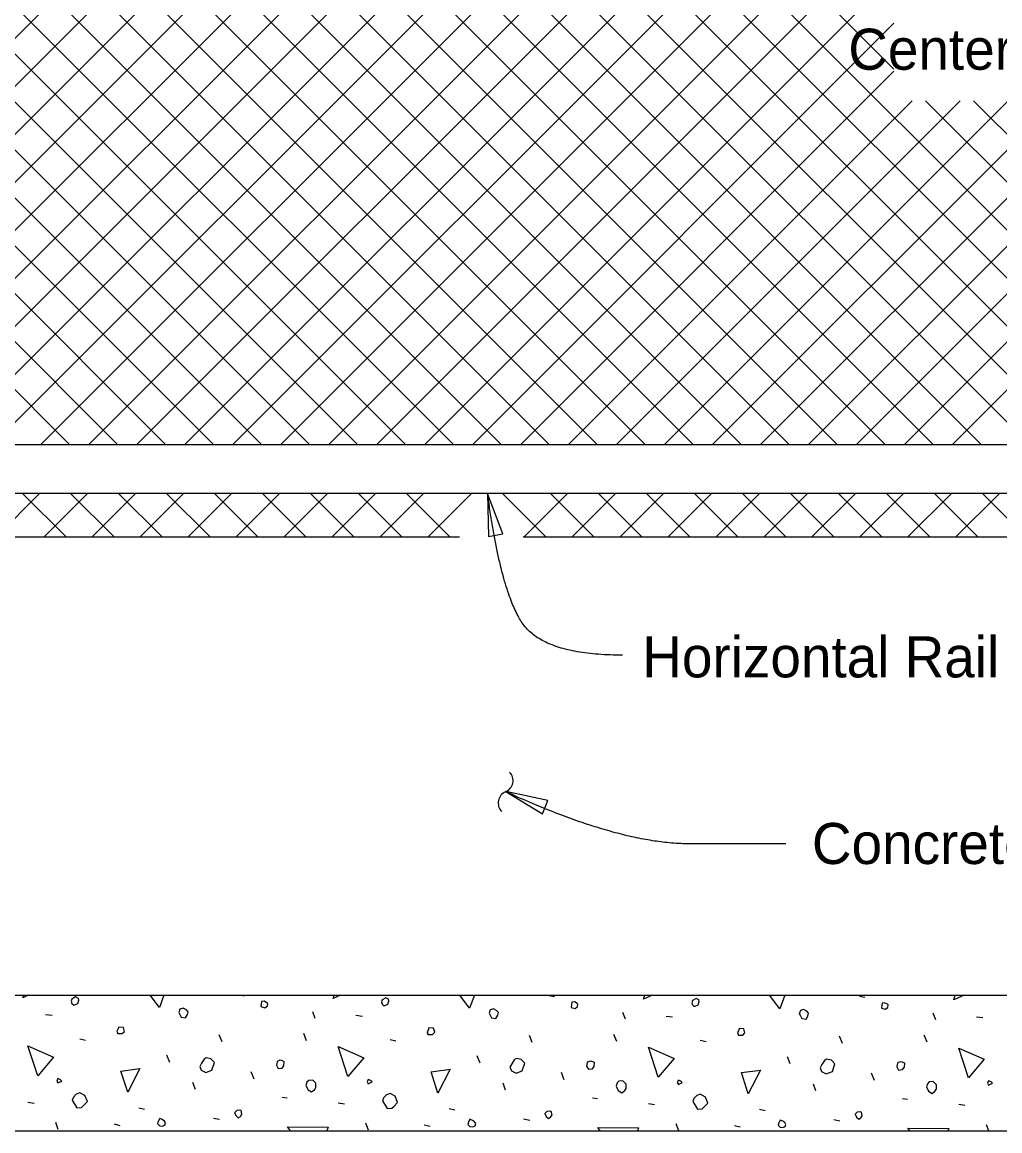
# Model space of a CAD drawing. Extents: x 0.4 to 38.5, y 1.2 to 25.4.
# Drawn here: x 3.07 to 7.87, y 14.04 to 19.49 of the extents above; entities that cross this region are included whole.
import ezdxf

# ---------------------------------------------------------------- set-up
doc = ezdxf.new("R2010")
doc.units = 0
for name, color, linetype in [('Dimension', 7, 'Continuous'), ('Miscellaneous', 7, 'Continuous'), ('SteelMisc', 7, 'Continuous'), ('SupstrConc', 7, 'Continuous'), ('TextStructures', 7, 'Continuous')]:
    doc.layers.add(name, color=color, linetype=linetype)

msp = doc.modelspace()

# ---------------------------------------------------------------- linework, layer by layer
at = {"layer": 'Dimension'}
for points in [[(5.3566, 17.1708), (5.3616, 16.9597), (5.4309, 16.9731)], [(5.4456, 15.7069), (5.6265, 15.5979), (5.6523, 15.6635)]]:
    msp.add_lwpolyline(points, close=True, dxfattribs=at)
for centre, start, end in [((5.4222, 15.7609), 292.7091, 44.4364), ((5.4682, 15.651), 112.7091, 224.4364)]:
    msp.add_arc(centre, 0.0596, start, end, dxfattribs=at)
for points in [[(6.0197, 16.3768), (5.6218, 16.3768), (5.4178, 16.7138), (5.3566, 17.1707)], [(6.8209, 15.4497), (6.7025, 15.4497), (6.0031, 15.4497), (5.4454, 15.7067)]]:
    msp.add_open_spline(points, degree=2, dxfattribs=at)
at = {"layer": 'Miscellaneous'}
for p, q in [((6.6877, 22.5875), (2.2208, 18.1206)), ((6.2163, 22.5875), (2.2208, 18.592)), ((6.452, 22.5875), (2.2208, 18.3563)), ((7.1591, 22.5875), (2.2208, 17.6492)), ((6.9234, 22.5875), (2.2208, 17.8849)), ((7.3948, 22.5875), (2.2704, 17.4631)), ((7.5471, 17.4104), (2.3872, 22.5703)), ((7.6305, 22.5875), (2.4688, 17.4258)), ((7.7828, 17.4104), (2.6043, 22.5889)), ((7.8662, 22.5875), (2.6891, 17.4104)), ((8.0185, 17.4104), (2.8414, 22.5875)), ((8.1019, 22.5875), (2.9248, 17.4104)), ((8.2542, 17.4104), (3.0771, 22.5875)), ((8.3376, 22.5875), (3.1605, 17.4104)), ((8.4899, 17.4104), (3.3128, 22.5875)), ((8.5733, 22.5875), (3.3962, 17.4104)), ((8.7256, 17.4104), (3.5485, 22.5875)), ((8.809, 22.5875), (3.6319, 17.4104)), ((8.9613, 17.4104), (3.7842, 22.5875)), ((9.0447, 22.5875), (3.8676, 17.4104)), ((7.352, 19.2554), (4.0199, 22.5875)), ((9.2804, 22.5875), (4.1033, 17.4104)), ((7.3114, 17.4104), (2.2208, 22.501)), ((7.0757, 17.4104), (2.2208, 22.2653)), ((6.84, 17.4104), (2.2208, 22.0296)), ((6.6043, 17.4104), (2.2208, 21.7939)), ((6.3686, 17.4104), (2.2208, 21.5582)), ((6.1329, 17.4104), (2.2208, 21.3225)), ((5.8972, 17.4104), (2.2208, 21.0868)), ((5.6615, 17.4104), (2.2208, 20.8511)), ((5.4258, 17.4104), (2.2208, 20.6154)), ((7.352, 20.4234), (4.339, 17.4104)), ((5.1901, 17.4104), (2.2208, 20.3797)), ((7.352, 20.1877), (4.5747, 17.4104)), ((4.9544, 17.4104), (2.2208, 20.1439)), ((7.352, 19.952), (4.8104, 17.4104)), ((4.7187, 17.4104), (2.2208, 19.9082)), ((7.352, 19.7163), (5.0461, 17.4104)), ((4.483, 17.4104), (2.2208, 19.6725)), ((7.352, 19.4806), (5.2818, 17.4104)), ((4.2473, 17.4104), (2.2208, 19.4368)), ((7.352, 19.2449), (5.5175, 17.4104)), ((4.0116, 17.4104), (2.2208, 19.2011)), ((7.4426, 19.0998), (5.7532, 17.4104)), ((7.6783, 19.0998), (5.9889, 17.4104)), ((7.914, 19.0998), (6.2246, 17.4104)), ((8.1497, 19.0998), (6.4603, 17.4104)), ((8.3854, 19.0998), (6.696, 17.4104)), ((8.6211, 19.0998), (6.9317, 17.4104)), ((8.8568, 19.0998), (7.1674, 17.4104)), ((9.0925, 19.0998), (7.4031, 17.4104)), ((9.197, 17.4104), (7.5077, 19.0998)), ((9.3282, 19.0998), (7.6388, 17.4104)), ((9.4327, 17.4104), (7.7434, 19.0998)), ((3.7759, 17.4104), (2.2208, 18.9654)), ((3.5402, 17.4104), (2.2208, 18.7297)), ((3.3045, 17.4104), (2.2208, 18.494)), ((3.1566, 17.1708), (2.943, 16.9573)), ((3.2862, 16.9573), (3.0727, 17.1708)), ((3.3923, 17.1708), (3.1788, 16.9573)), ((3.5219, 16.9573), (3.3084, 17.1708)), ((3.628, 17.1708), (3.4145, 16.9573)), ((3.7576, 16.9573), (3.5441, 17.1708)), ((3.8637, 17.1708), (3.6502, 16.9573)), ((3.9933, 16.9573), (3.7798, 17.1708)), ((4.0994, 17.1708), (3.8859, 16.9573)), ((4.229, 16.9573), (4.0155, 17.1708)), ((4.3351, 17.1708), (4.1216, 16.9573)), ((4.4647, 16.9573), (4.2512, 17.1708)), ((4.5708, 17.1708), (4.3573, 16.9573)), ((4.7004, 16.9573), (4.4869, 17.1708)), ((4.8065, 17.1708), (4.593, 16.9573)), ((4.9361, 16.9573), (4.7226, 17.1708)), ((5.0422, 17.1708), (4.8287, 16.9573)), ((5.1718, 16.9573), (4.9583, 17.1708)), ((5.2779, 17.1708), (5.0644, 16.9573)), ((5.6432, 16.9573), (5.4297, 17.1708)), ((5.7493, 17.1708), (5.5358, 16.9573)), ((5.8789, 16.9573), (5.6654, 17.1708)), ((5.985, 17.1708), (5.7715, 16.9573)), ((6.1146, 16.9573), (5.9011, 17.1708)), ((6.2207, 17.1708), (6.0072, 16.9573)), ((6.3503, 16.9573), (6.1368, 17.1708)), ((6.4564, 17.1708), (6.2429, 16.9573)), ((6.586, 16.9573), (6.3725, 17.1708)), ((6.6921, 17.1708), (6.4786, 16.9573)), ((6.8217, 16.9573), (6.6082, 17.1708)), ((6.9278, 17.1708), (6.7143, 16.9573)), ((7.0574, 16.9573), (6.8439, 17.1708)), ((7.1635, 17.1708), (6.95, 16.9573)), ((7.2931, 16.9573), (7.0796, 17.1708)), ((7.3992, 17.1708), (7.1857, 16.9573)), ((7.5288, 16.9573), (7.3153, 17.1708)), ((7.6349, 17.1708), (7.4214, 16.9573)), ((7.7645, 16.9573), (7.551, 17.1708)), ((7.8706, 17.1708), (7.6571, 16.9573)), ((8.0002, 16.9573), (7.7867, 17.1708)), ((4.143, 14.7072), (4.1618, 14.7035)), ((5.6591, 14.7053), (5.6856, 14.7)), ((7.1829, 14.7017), (7.2094, 14.6964)), ((3.1859, 14.6116), (3.2178, 14.608)), ((4.51, 14.5921), (4.4976, 14.6257)), ((4.7098, 14.608), (4.7416, 14.6045)), ((6.0338, 14.5886), (6.0214, 14.6222)), ((6.2336, 14.6045), (6.2654, 14.601)), ((7.5576, 14.585), (7.5453, 14.6186)), ((7.7574, 14.601), (7.7892, 14.5974)), ((3.3539, 14.4931), (3.3822, 14.4861)), ((4.0522, 14.4772), (4.038, 14.5126)), ((4.4676, 14.4825), (4.4534, 14.5179)), ((4.8777, 14.4896), (4.906, 14.4825)), ((5.576, 14.4737), (5.5618, 14.509)), ((5.9914, 14.479), (5.9773, 14.5143)), ((6.4015, 14.4861), (6.4298, 14.479)), ((7.0998, 14.4701), (7.0856, 14.5055)), ((7.5152, 14.4754), (7.5011, 14.5108)), ((3.7958, 14.3765), (3.7817, 14.4118)), ((5.3196, 14.3729), (5.3055, 14.4083)), ((6.8435, 14.3694), (6.8293, 14.4047)), ((4.2095, 14.2951), (4.1953, 14.3305)), ((5.7333, 14.2916), (5.7192, 14.327)), ((7.2571, 14.2881), (7.243, 14.3234)), ((3.9213, 14.2439), (3.909, 14.2775)), ((5.4452, 14.2403), (5.4328, 14.2739)), ((6.969, 14.2368), (6.9566, 14.2704)), ((3.0993, 14.182), (3.1294, 14.1767)), ((4.3474, 14.2067), (4.3721, 14.2032)), ((4.6231, 14.1785), (4.6532, 14.1732)), ((5.8712, 14.2032), (5.8959, 14.1997)), ((6.147, 14.1749), (6.177, 14.1696)), ((7.395, 14.1997), (7.4198, 14.1961)), ((7.6708, 14.1714), (7.7008, 14.1661)), ((3.6438, 14.1537), (3.6721, 14.1466)), ((5.1676, 14.1502), (5.1959, 14.1431)), ((6.6914, 14.1466), (6.7197, 14.1396)), ((3.2478, 14.0476), (3.2354, 14.0812)), ((3.5218, 14.0742), (3.5501, 14.0671)), ((4.0097, 14.1024), (4.0398, 14.0971)), ((4.7716, 14.0441), (4.7593, 14.0777)), ((5.0456, 14.0706), (5.0739, 14.0636)), ((5.5335, 14.0989), (5.5636, 14.0936)), ((6.2955, 14.0406), (6.2831, 14.0742)), ((6.5695, 14.0671), (6.5977, 14.06)), ((7.0574, 14.0954), (7.0874, 14.0901)), ((7.818, 14.0406), (7.8069, 14.0706))]:
    msp.add_line(p, q, dxfattribs=at)
for points in [[(3.0746, 14.6946), (3.0785, 14.7072)], [(3.1026, 14.7072), (3.0746, 14.6946)], [(3.7446, 14.6469), (3.6987, 14.7072)], [(3.7671, 14.7072), (3.7446, 14.6469)], [(4.5984, 14.6911), (4.6034, 14.7072)], [(4.6343, 14.7072), (4.5984, 14.6911)], [(5.2684, 14.6434), (5.2198, 14.7072)], [(5.2922, 14.7072), (5.2684, 14.6434)], [(6.1222, 14.6876), (6.1283, 14.7072)], [(6.166, 14.7072), (6.1222, 14.6876)], [(6.7922, 14.6398), (6.741, 14.7072)], [(6.8174, 14.7072), (6.7922, 14.6398)], [(7.646, 14.684), (7.6532, 14.7072)], [(7.6977, 14.7072), (7.646, 14.684)], [(3.3221, 14.6593), (3.3291, 14.6593), (3.3433, 14.6664), (3.3486, 14.6823), (3.3468, 14.6911), (3.3327, 14.6982), (3.315, 14.6876), (3.3115, 14.677), (3.315, 14.6664), (3.3221, 14.6593)], [(4.2431, 14.6505), (4.2625, 14.6452), (4.2749, 14.654), (4.2767, 14.6664), (4.2731, 14.6699), (4.259, 14.677), (4.2466, 14.6752), (4.2448, 14.6628), (4.2431, 14.6505)], [(4.8459, 14.6558), (4.853, 14.6558), (4.8671, 14.6628), (4.8724, 14.6787), (4.8706, 14.6876), (4.8565, 14.6946), (4.8388, 14.684), (4.8353, 14.6734), (4.8388, 14.6628), (4.8459, 14.6558)], [(5.7669, 14.6469), (5.7863, 14.6416), (5.7987, 14.6505), (5.8005, 14.6628), (5.7969, 14.6664), (5.7828, 14.6734), (5.7704, 14.6717), (5.7687, 14.6593), (5.7669, 14.6469)], [(6.3697, 14.6522), (6.3768, 14.6522), (6.3909, 14.6593), (6.3962, 14.6752), (6.3944, 14.684), (6.3803, 14.6911), (6.3626, 14.6805), (6.3591, 14.6699), (6.3626, 14.6593), (6.3697, 14.6522)], [(7.2907, 14.6434), (7.3101, 14.6381), (7.3225, 14.6469), (7.3243, 14.6593), (7.3208, 14.6628), (7.3066, 14.6699), (7.2942, 14.6681), (7.2925, 14.6558), (7.2907, 14.6434)], [(3.8436, 14.6151), (3.8524, 14.5992), (3.8736, 14.5957), (3.8824, 14.6116), (3.886, 14.6257), (3.8771, 14.6345), (3.8612, 14.6434), (3.8453, 14.6381), (3.84, 14.6222), (3.8436, 14.6151)], [(5.3674, 14.6116), (5.3762, 14.5957), (5.3974, 14.5921), (5.4063, 14.608), (5.4098, 14.6222), (5.401, 14.631), (5.3851, 14.6398), (5.3691, 14.6345), (5.3638, 14.6186), (5.3674, 14.6116)], [(6.8912, 14.608), (6.9, 14.5921), (6.9212, 14.5886), (6.9301, 14.6045), (6.9336, 14.6186), (6.9248, 14.6275), (6.9089, 14.6363), (6.893, 14.631), (6.8877, 14.6151), (6.8912, 14.608)], [(3.5413, 14.5179), (3.5625, 14.5179), (3.5731, 14.5285), (3.5678, 14.5479), (3.5448, 14.5497), (3.5413, 14.5391), (3.536, 14.5302), (3.5413, 14.5179), (3.5377, 14.5214)], [(5.0651, 14.5143), (5.0863, 14.5143), (5.0969, 14.5249), (5.0916, 14.5444), (5.0686, 14.5462), (5.0651, 14.5355), (5.0598, 14.5267), (5.0651, 14.5143), (5.0616, 14.5179)], [(6.5889, 14.5108), (6.6101, 14.5108), (6.6207, 14.5214), (6.6154, 14.5409), (6.5924, 14.5426), (6.5889, 14.532), (6.5836, 14.5232), (6.5889, 14.5108), (6.5854, 14.5143)], [(3.1471, 14.311), (3.0993, 14.4578), (3.2248, 14.403), (3.1471, 14.311)], [(4.6709, 14.3075), (4.6231, 14.4542), (4.7487, 14.3994), (4.6709, 14.3075)], [(6.1947, 14.304), (6.147, 14.4507), (6.2725, 14.3959), (6.1947, 14.304)], [(7.7185, 14.3004), (7.6708, 14.4472), (7.7963, 14.3924), (7.7185, 14.3004)], [(3.9496, 14.3393), (3.9726, 14.327), (4.0027, 14.3393), (4.015, 14.3765), (3.9974, 14.3941), (3.9744, 14.3994), (3.9638, 14.3924), (3.9514, 14.3729), (3.9426, 14.357), (3.9496, 14.3393)], [(4.3191, 14.3623), (4.3279, 14.3464), (4.3474, 14.3482), (4.3562, 14.3605), (4.358, 14.38), (4.3456, 14.3853), (4.3368, 14.3871), (4.3262, 14.3835), (4.3226, 14.38), (4.3191, 14.3623)], [(5.4734, 14.3358), (5.4964, 14.3234), (5.5265, 14.3358), (5.5388, 14.3729), (5.5212, 14.3906), (5.4982, 14.3959), (5.4876, 14.3888), (5.4752, 14.3694), (5.4664, 14.3535), (5.4734, 14.3358)], [(5.8429, 14.3588), (5.8517, 14.3429), (5.8712, 14.3446), (5.88, 14.357), (5.8818, 14.3765), (5.8694, 14.3818), (5.8606, 14.3835), (5.85, 14.38), (5.8464, 14.3765), (5.8429, 14.3588)], [(6.9973, 14.3323), (7.0202, 14.3199), (7.0503, 14.3323), (7.0627, 14.3694), (7.045, 14.3871), (7.022, 14.3924), (7.0114, 14.3853), (6.999, 14.3658), (6.9902, 14.3499), (6.9973, 14.3323)], [(7.3667, 14.3552), (7.3756, 14.3393), (7.395, 14.3411), (7.4038, 14.3535), (7.4056, 14.3729), (7.3932, 14.3782), (7.3844, 14.38), (7.3738, 14.3765), (7.3703, 14.3729), (7.3667, 14.3552)], [(3.589, 14.2297), (3.5554, 14.334), (3.6491, 14.3464), (3.589, 14.2297)], [(5.1128, 14.2262), (5.0792, 14.3305), (5.1729, 14.3429), (5.1128, 14.2262)], [(6.6366, 14.2227), (6.603, 14.327), (6.6967, 14.3393), (6.6366, 14.2227)], [(3.2461, 14.2757), (3.2655, 14.2845), (3.2584, 14.2916), (3.2461, 14.2969), (3.2408, 14.2845), (3.2461, 14.2757)], [(4.464, 14.2633), (4.4747, 14.2421), (4.4923, 14.2315), (4.5065, 14.2421), (4.5135, 14.2527), (4.5135, 14.2739), (4.4976, 14.2898), (4.4782, 14.2881), (4.4693, 14.2792), (4.464, 14.2633)], [(4.7699, 14.2722), (4.7893, 14.281), (4.7822, 14.2881), (4.7699, 14.2934), (4.7646, 14.281), (4.7699, 14.2722)], [(5.9879, 14.2598), (5.9985, 14.2386), (6.0161, 14.228), (6.0303, 14.2386), (6.0374, 14.2492), (6.0374, 14.2704), (6.0214, 14.2863), (6.002, 14.2845), (5.9932, 14.2757), (5.9879, 14.2598)], [(6.2937, 14.2686), (6.3131, 14.2775), (6.3061, 14.2845), (6.2937, 14.2898), (6.2884, 14.2775), (6.2937, 14.2686)], [(7.5117, 14.2562), (7.5223, 14.235), (7.54, 14.2244), (7.5541, 14.235), (7.5612, 14.2456), (7.5612, 14.2668), (7.5453, 14.2828), (7.5258, 14.281), (7.517, 14.2722), (7.5117, 14.2562)], [(7.8175, 14.2651), (7.8369, 14.2739), (7.8299, 14.281), (7.8175, 14.2863), (7.8122, 14.2739), (7.8175, 14.2651)], [(3.3168, 14.1908), (3.3397, 14.1537), (3.3627, 14.1555), (3.3716, 14.1643), (3.391, 14.1838), (3.3786, 14.2138), (3.3539, 14.228), (3.3362, 14.2209), (3.3221, 14.2067), (3.3168, 14.1908)], [(4.8406, 14.1873), (4.8636, 14.1502), (4.8865, 14.1519), (4.8954, 14.1608), (4.9148, 14.1802), (4.9025, 14.2103), (4.8777, 14.2244), (4.86, 14.2174), (4.8459, 14.2032), (4.8406, 14.1873)], [(6.3644, 14.1838), (6.3874, 14.1466), (6.4104, 14.1484), (6.4192, 14.1572), (6.4386, 14.1767), (6.4263, 14.2067), (6.4015, 14.2209), (6.3838, 14.2138), (6.3697, 14.1997), (6.3644, 14.1838)], [(4.1211, 14.1148), (4.1317, 14.1042), (4.1423, 14.1113), (4.1494, 14.1219), (4.1458, 14.1396), (4.137, 14.1413), (4.1246, 14.1396), (4.114, 14.129), (4.1211, 14.1148)], [(5.6449, 14.1113), (5.6555, 14.1007), (5.6661, 14.1077), (5.6732, 14.1184), (5.6697, 14.136), (5.6608, 14.1378), (5.6484, 14.136), (5.6378, 14.1254), (5.6449, 14.1113)], [(7.1687, 14.1077), (7.1793, 14.0971), (7.1899, 14.1042), (7.197, 14.1148), (7.1935, 14.1325), (7.1846, 14.1343), (7.1723, 14.1325), (7.1617, 14.1219), (7.1687, 14.1077)], [(3.7463, 14.0653), (3.7587, 14.0636), (3.7711, 14.0689), (3.7746, 14.0795), (3.7693, 14.0883), (3.7587, 14.0954), (3.7463, 14.1007), (3.7393, 14.0865), (3.7357, 14.0759), (3.7463, 14.0653)], [(4.3887, 14.0406), (4.3739, 14.06), (4.5736, 14.0583), (4.567, 14.0406)], [(5.2701, 14.0618), (5.2825, 14.06), (5.2949, 14.0653), (5.2984, 14.0759), (5.2931, 14.0848), (5.2825, 14.0918), (5.2701, 14.0971), (5.2631, 14.083), (5.2595, 14.0724), (5.2701, 14.0618)], [(5.9098, 14.0406), (5.8977, 14.0565), (6.0975, 14.0547), (6.0922, 14.0406)], [(6.794, 14.0583), (6.8063, 14.0565), (6.8187, 14.0618), (6.8222, 14.0724), (6.8169, 14.0812), (6.8063, 14.0883), (6.794, 14.0936), (6.7869, 14.0795), (6.7834, 14.0689), (6.794, 14.0583)], [(7.4309, 14.0406), (7.4215, 14.0529), (7.6213, 14.0512), (7.6173, 14.0406)]]:
    msp.add_lwpolyline(points, dxfattribs=at)
at = {"layer": 'SteelMisc'}
for p, q in [((11.5457, 17.4104), (2.6043, 17.4104)), ((11.5457, 17.1708), (2.6043, 17.1708))]:
    msp.add_line(p, q, dxfattribs=at)
at = {"layer": 'SupstrConc'}
for p, q in [((0.6881, 16.9573), (5.2184, 16.9573)), ((5.5315, 16.9573), (18.6893, 16.9573)), ((0.6881, 14.7072), (23.462, 14.7072)), ((0.6881, 14.0406), (23.462, 14.0406))]:
    msp.add_line(p, q, dxfattribs=at)

# ---------------------------------------------------------------- texts
at = {"layer": 'TextStructures'}
for s, p in [('Centers)  (Typ.)', (7.1282, 19.2522)), ('Horizontal Rail', (6.1165, 16.2676)), ('Concrete Parapet', (6.9497, 15.351))]:
    msp.add_text(s, height=0.2016, dxfattribs=at).set_placement(p)

doc.saveas('drawing.dxf')
